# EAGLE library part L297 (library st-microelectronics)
STEPPER MOTOR CONTROLLER
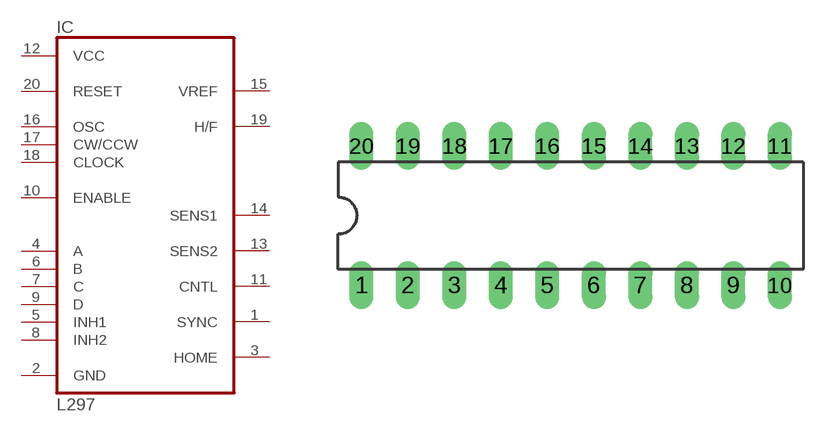
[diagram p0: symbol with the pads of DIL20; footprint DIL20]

Designator prefix IC

## L297 (MPN: L297/1; OC_FARNELL: 1094209; OC_NEWARK: 56P8258)  [DIL20]
1  SYNC  out
2  GND  pwr
3  HOME  out
4  A  out
5  INH1  out
6  B  out
7  C  out
8  INH2  out
9  D  out
10  ENABLE  in
11  CNTL  in
12  VCC  pwr
13  SENS2  out
14  SENS1  out
15  VREF  in
16  OSC
17  CW/CCW  in
18  CLOCK  in
19  H/F  in
20  RESET  in

## Footprint DIL20 (pad centres in mm)
Dual In Line Package
drill 0.813 long: 1 -11.43,-3.81; 2 -8.89,-3.81; 3 -6.35,-3.81; 4 -3.81,-3.81; 5 -1.27,-3.81; 6 1.27,-3.81; 7 3.81,-3.81; 8 6.35,-3.81; 9 8.89,-3.81; 10 11.43,-3.81; 11 11.43,3.81; 12 8.89,3.81; 13 6.35,3.81; 14 3.81,3.81; 15 1.27,3.81; 16 -1.27,3.81; 17 -3.81,3.81; 18 -6.35,3.81; 19 -8.89,3.81; 20 -11.43,3.81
